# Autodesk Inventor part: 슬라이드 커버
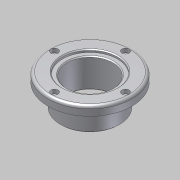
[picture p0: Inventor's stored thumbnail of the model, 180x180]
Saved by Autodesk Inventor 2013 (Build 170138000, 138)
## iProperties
Created: 2013-06
Part Number: 슬라이드 커버
Document SubType Name: Modeling
Designer: SeoGD™[esajin.kr]
Density: 1 g/cm^3
Material: 일반
Mass: 75.9731 g
Surface Area: 227.998 cm^2
Volume: 75.9731 cm^3
Author: SeoGD™[esajin.kr]
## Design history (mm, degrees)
sketch "스케치1"
  geometry: C1 r 46 at (0, -39.25) reference; C2 r 32.5 at (0, -39.25) reference; 1 further point
  node "참조1"
  node "참조2"
extrude "돌출1" new body sketch "스케치1" distance "d0" = 10; taper "d1" = 0 deg
extrude "돌출2" join sketch "스케치1" distance "d2" = 25; taper "d3" = 0 deg
hole "구멍1" diameter "d6" = 50; stored, may be unused: countersink angle "d10" = 90 deg, drill point angle "d12" = 118 deg; dims "d4" = 10, "d5" = 10, "d7" = 6, "d8" = 4, "d9" = 2, "d11" = 8
sketch "스케치2"
  geometry: C1 r 46 at (0, 0) reference; C2 r 1.621 at (0, 39) reference; C3 r 1.621 at (39, 0) reference; C4 r 1.621 at (0, -39) reference; C5 r 1.621 at (-39, 0) reference; C6 r 33.5 at (0, 0) reference; 1 further point
hole "구멍2" sketch "스케치2" at (0, 39) diameter "d13" = 4.5; stored, may be unused: countersink angle "d17" = 90 deg, drill point angle "d19" = 118 deg; dims "d14" = 6, "d15" = 8, "d16" = 4.4, "d18" = 8
fillet "모깎기1" dims "d23" = 3
chamfer "모따기1" distance "d24" = 1; stored, may be unused: second distance "d25" = 2, angle "d26" = 45 deg
sketch "스케치3"
  geometry: C1 r 25 at (39, 0) reference; C2 r 30 at (39, 0); 1 further point
  constraints: 1 centre point, 1 coincident
  dimensions: "d27" = 60 diameter of C2
extrude "돌출3" cut sketch "스케치3" distance "d28" = 3; taper "d29" = 0 deg
chamfer "모따기2" distance "d30" = 1; stored, may be unused: second distance "d31" = 2, angle "d32" = 45 deg
node "솔리드1"
pattern_circular "원형 패턴1" dims angle "d21" = 360 deg
node "참조3"
